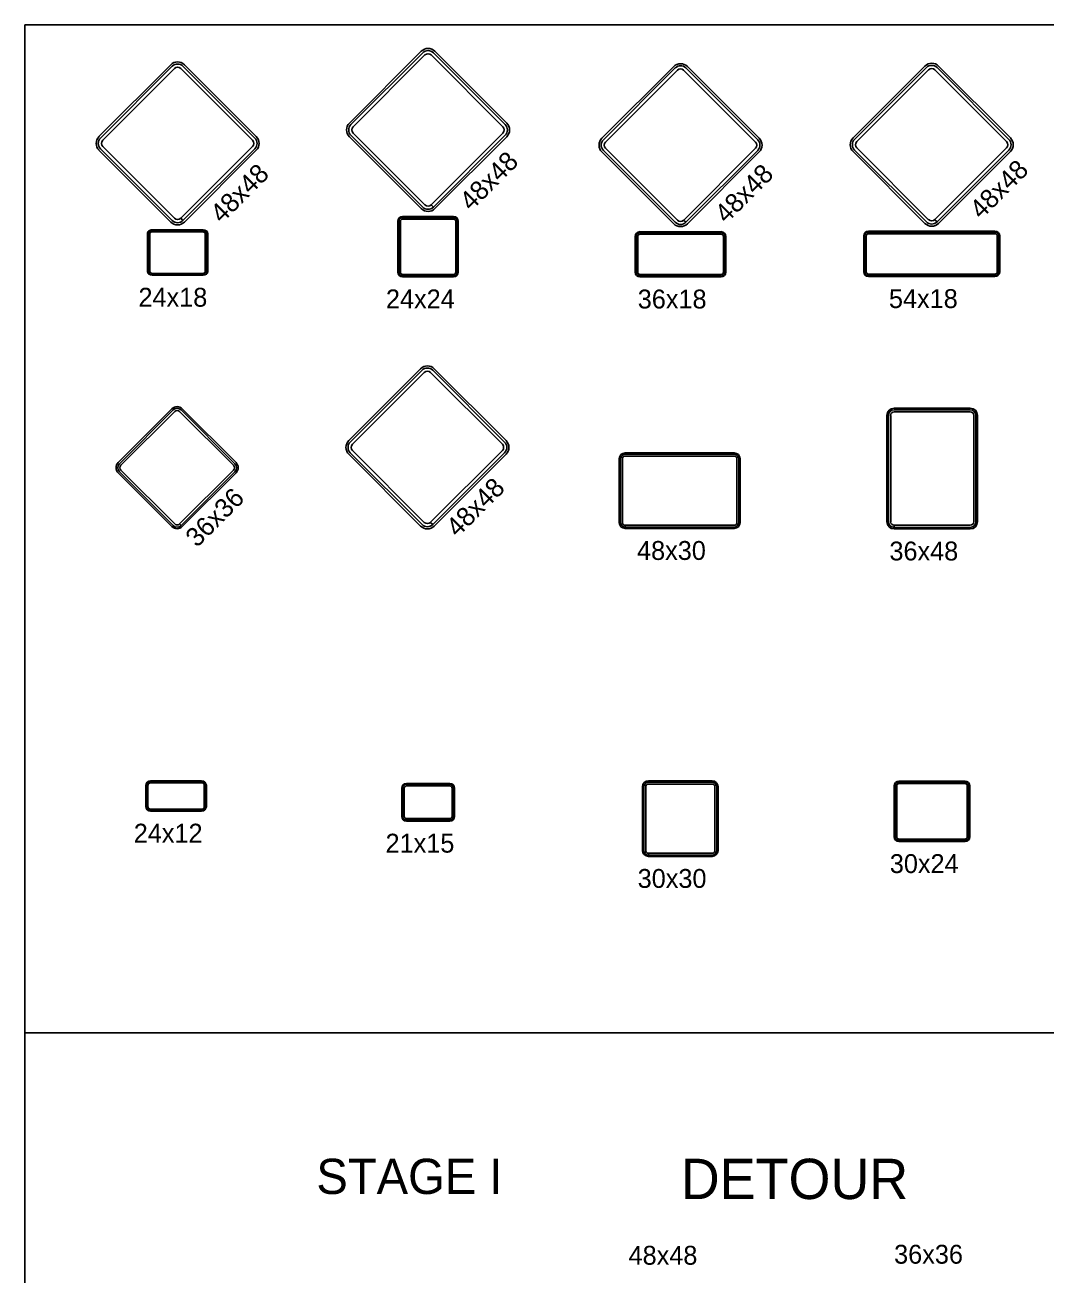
# Model space of a CAD drawing. Extents: x 1458 to 4498, y 17709 to 24109.
# Drawn here: x 1458 to 2268, y 18718 to 19709 of the extents above; entities that cross this region are included whole.
import ezdxf

# ---------------------------------------------------------------- set-up
doc = ezdxf.new("R2010")
doc.units = 0
for name, color, linetype in [('P_ODOT_PLAN_TBlock', 7, 'Continuous'), ('P_TRAF_TCP_General', 7, 'Continuous'), ('P_TRAF_TCP_GeneralTx', 7, 'Continuous')]:
    doc.layers.add(name, color=color, linetype=linetype)

msp = doc.modelspace()

# ---------------------------------------------------------------- linework, layer by layer
at = {"layer": 'P_ODOT_PLAN_TBlock'}
msp.add_line((1458.44, 18909.14), (2578.44, 18909.14), dxfattribs=at)
at = {"layer": 'P_TRAF_TCP_General'}
for p, q in [((1773.03, 19688.26), (1716.02, 19631.26)), ((1774.21, 19687.08), (1717.21, 19630.07)), ((1718.97, 19628.31), (1775.98, 19685.31)), ((1780.93, 19685.31), (1837.93, 19628.31)), ((1839.7, 19630.07), (1782.69, 19687.08)), ((1840.88, 19631.26), (1783.88, 19688.26)), ((1574.21, 19677.59), (1517.2, 19620.58)), ((1575.39, 19676.4), (1518.39, 19619.4)), ((1520.15, 19617.63), (1577.16, 19674.64)), ((1582.11, 19674.64), (1639.11, 19617.63)), ((1640.88, 19619.4), (1583.87, 19676.4)), ((1642.06, 19620.58), (1585.06, 19677.59)), ((1973.46, 19676.17), (1916.46, 19619.17)), ((1974.64, 19674.99), (1917.64, 19617.98)), ((1919.41, 19616.21), (1976.41, 19673.22)), ((1981.36, 19673.22), (2038.37, 19616.21)), ((1981.36, 19673.22), (2038.37, 19616.21)), ((2040.13, 19617.98), (1983.13, 19674.99)), ((2041.32, 19619.17), (1984.31, 19676.17)), ((2172.87, 19676.5), (2115.86, 19619.5)), ((2174.05, 19675.32), (2117.04, 19618.31)), ((2118.81, 19616.54), (2175.82, 19673.55)), ((2180.76, 19673.55), (2237.77, 19616.54)), ((2239.54, 19618.31), (2182.53, 19675.32)), ((2240.72, 19619.5), (2183.72, 19676.5)), ((1775.98, 19566.35), (1718.97, 19623.36)), ((1837.93, 19623.36), (1780.94, 19566.37)), ((1577.16, 19555.68), (1520.15, 19612.68)), ((1577.16, 19555.68), (1520.15, 19612.68)), ((1639.11, 19612.68), (1582.12, 19555.7)), ((1716.02, 19620.41), (1773.03, 19563.4)), ((1717.21, 19621.59), (1774.21, 19564.59)), ((1782.71, 19564.61), (1839.7, 19621.59)), ((1783.88, 19563.4), (1840.88, 19620.41)), ((1517.2, 19609.73), (1574.21, 19552.73)), ((1518.39, 19610.92), (1575.39, 19553.91)), ((1583.89, 19553.93), (1640.88, 19610.92)), ((1585.06, 19552.73), (1642.06, 19609.73)), ((1916.46, 19608.32), (1973.46, 19551.31)), ((1917.64, 19609.5), (1974.64, 19552.49)), ((1976.41, 19554.26), (1919.41, 19611.27)), ((2038.37, 19611.27), (1981.38, 19554.28)), ((1983.14, 19552.51), (2040.13, 19609.5)), ((1984.31, 19551.31), (2041.32, 19608.32)), ((2115.86, 19608.65), (2172.87, 19551.64)), ((2117.04, 19609.83), (2174.05, 19552.82)), ((2175.82, 19554.59), (2118.81, 19611.6)), ((2237.77, 19611.6), (2180.78, 19554.61)), ((2182.55, 19552.84), (2239.54, 19609.83)), ((2183.72, 19551.64), (2240.72, 19608.65)), ((1782.69, 19564.59), (1780.93, 19566.35)), ((1782.69, 19564.59), (1780.93, 19566.35)), ((1780.94, 19566.37), (1782.71, 19564.61)), ((1780.94, 19566.37), (1782.71, 19564.61)), ((1583.87, 19553.91), (1582.11, 19555.68)), ((1583.87, 19553.91), (1582.11, 19555.68)), ((1582.12, 19555.7), (1583.89, 19553.93)), ((1582.12, 19555.7), (1583.89, 19553.93)), ((1754.46, 19553.36), (1754.46, 19512.98)), ((1755.26, 19553.3), (1755.26, 19512.92)), ((1755.26, 19553.3), (1755.26, 19512.92)), ((1756.51, 19512.92), (1756.51, 19553.3)), ((1798.64, 19557.16), (1758.26, 19557.16)), ((1798.64, 19556.3), (1758.26, 19556.3)), ((1798.64, 19556.3), (1758.26, 19556.3)), ((1758.26, 19555.05), (1798.64, 19555.05)), ((1800.39, 19553.3), (1800.39, 19512.92)), ((1801.64, 19512.92), (1801.64, 19553.3)), ((1801.64, 19512.92), (1801.64, 19553.3)), ((1802.44, 19512.98), (1802.44, 19553.36)), ((1983.13, 19552.49), (1981.36, 19554.26)), ((1983.13, 19552.49), (1981.36, 19554.26)), ((1981.38, 19554.28), (1983.14, 19552.51)), ((1981.38, 19554.28), (1983.14, 19552.51)), ((2182.53, 19552.82), (2180.76, 19554.59)), ((2182.53, 19552.82), (2180.76, 19554.59)), ((2180.78, 19554.61), (2182.55, 19552.84)), ((2180.78, 19554.61), (2182.55, 19552.84)), ((1555.64, 19543.63), (1555.64, 19513.34)), ((1556.44, 19543.59), (1556.44, 19513.3)), ((1557.69, 19513.3), (1557.69, 19543.59)), ((1599.82, 19546.48), (1559.44, 19546.48)), ((1599.82, 19545.84), (1559.44, 19545.84)), ((1559.44, 19544.9), (1599.82, 19544.9)), ((1601.57, 19543.59), (1601.57, 19513.3)), ((1602.82, 19513.3), (1602.82, 19543.59)), ((1603.62, 19513.34), (1603.62, 19543.63)), ((2011.12, 19545.06), (1946.65, 19545.06)), ((2011.12, 19544.32), (1946.65, 19544.32)), ((1946.65, 19543.07), (2011.12, 19543.07)), ((2228.52, 19545.4), (2128.06, 19545.4)), ((2228.52, 19544.65), (2128.06, 19544.65)), ((2228.52, 19543.4), (2128.06, 19543.4)), ((2128.06, 19543.4), (2228.52, 19543.4)), ((1942.9, 19541.32), (1942.9, 19512.83)), ((1943.65, 19541.32), (1943.65, 19512.83)), ((1944.9, 19512.83), (1944.9, 19541.32)), ((2012.87, 19541.32), (2012.87, 19512.83)), ((2014.12, 19512.83), (2014.12, 19541.32)), ((2014.87, 19512.83), (2014.87, 19541.32)), ((2124.31, 19541.65), (2124.31, 19513.16)), ((2125.06, 19541.65), (2125.06, 19513.16)), ((2126.31, 19541.65), (2126.31, 19513.16)), ((2126.31, 19513.16), (2126.31, 19541.65)), ((2230.27, 19513.16), (2230.27, 19541.65)), ((2230.27, 19541.65), (2230.27, 19513.16)), ((2231.52, 19513.16), (2231.52, 19541.65)), ((2232.27, 19513.16), (2232.27, 19541.65)), ((1559.44, 19511.05), (1559.44, 19511.99)), ((1559.44, 19510.5), (1599.82, 19510.5)), ((1599.82, 19511.99), (1559.45, 19511.99)), ((1559.45, 19511.99), (1559.45, 19511.05)), ((1559.45, 19511.05), (1599.82, 19511.05)), ((1758.26, 19509.92), (1758.26, 19511.17)), ((1758.26, 19509.92), (1798.64, 19509.92)), ((1758.26, 19509.18), (1798.64, 19509.18)), ((1798.64, 19511.17), (1758.27, 19511.17)), ((1758.27, 19511.17), (1758.27, 19509.92)), ((1758.27, 19509.92), (1798.64, 19509.92)), ((1946.65, 19509.83), (1946.65, 19511.08)), ((1946.65, 19509.08), (2011.12, 19509.08)), ((2011.12, 19511.08), (1946.66, 19511.08)), ((1946.66, 19511.08), (1946.66, 19509.83)), ((1946.66, 19509.83), (2011.12, 19509.83)), ((2128.06, 19511.41), (2228.52, 19511.41)), ((2128.06, 19510.16), (2128.06, 19511.41)), ((2128.06, 19509.41), (2228.52, 19509.41)), ((2228.52, 19511.41), (2128.07, 19511.41)), ((2128.07, 19511.41), (2128.07, 19510.16)), ((2128.07, 19510.16), (2228.52, 19510.16)), ((1772.53, 19436.24), (1715.52, 19379.23)), ((1773.71, 19435.05), (1716.71, 19378.05)), ((1839.2, 19378.05), (1782.19, 19435.05)), ((1840.38, 19379.23), (1783.38, 19436.24)), ((1718.47, 19376.28), (1775.48, 19433.29)), ((1780.43, 19433.29), (1837.43, 19376.28)), ((1575.12, 19404.48), (1532.43, 19361.79)), ((1626.01, 19361.79), (1583.32, 19404.48)), ((2208.93, 19405.01), (2148.45, 19405.01)), ((2208.93, 19403.76), (2148.45, 19403.76)), ((1576.04, 19403.56), (1533.35, 19360.87)), ((1576.04, 19403.56), (1533.35, 19360.87)), ((1534.58, 19359.63), (1577.28, 19402.33)), ((1581.16, 19402.33), (1623.86, 19359.63)), ((1625.09, 19360.87), (1582.4, 19403.56)), ((1625.09, 19360.87), (1582.4, 19403.56)), ((2142.71, 19399.26), (2142.71, 19314.79)), ((2143.96, 19399.26), (2143.96, 19314.79)), ((2145.71, 19314.79), (2145.71, 19399.26)), ((2148.45, 19402.01), (2208.93, 19402.01)), ((2211.68, 19399.26), (2211.68, 19314.79)), ((2213.43, 19314.79), (2213.43, 19399.26)), ((2214.68, 19314.79), (2214.68, 19399.26)), ((1715.52, 19368.38), (1772.53, 19311.38)), ((1716.71, 19369.56), (1773.71, 19312.56)), ((1716.71, 19369.56), (1773.71, 19312.56)), ((1775.48, 19314.33), (1718.47, 19371.33)), ((1837.43, 19371.33), (1780.44, 19314.34)), ((1782.21, 19312.58), (1839.2, 19369.56)), ((1783.38, 19311.38), (1840.38, 19368.38)), ((1930.21, 19364.71), (1930.21, 19314.23)), ((1931.21, 19364.71), (1931.21, 19314.23)), ((1932.71, 19314.23), (1932.71, 19364.71)), ((2021.42, 19369.45), (1934.95, 19369.45)), ((2021.42, 19368.46), (1934.95, 19368.46)), ((1934.95, 19366.96), (2021.42, 19366.96)), ((2023.67, 19364.71), (2023.67, 19314.23)), ((2025.17, 19314.23), (2025.17, 19364.71)), ((2026.17, 19314.23), (2026.17, 19364.71)), ((1533.35, 19354.51), (1576.04, 19311.82)), ((1533.35, 19354.51), (1576.04, 19311.82)), ((1577.28, 19313.05), (1534.58, 19355.75)), ((1623.86, 19355.75), (1581.18, 19313.07)), ((1582.4, 19311.82), (1625.09, 19354.51)), ((1582.41, 19311.83), (1625.09, 19354.51)), ((1532.43, 19353.59), (1575.12, 19310.9)), ((1583.32, 19310.9), (1626.01, 19353.59)), ((1582.4, 19311.82), (1581.16, 19313.05)), ((1581.18, 19313.07), (1582.41, 19311.83)), ((1782.19, 19312.56), (1780.43, 19314.33)), ((1782.19, 19312.56), (1780.43, 19314.33)), ((1780.44, 19314.34), (1782.21, 19312.58)), ((1780.44, 19314.34), (1782.21, 19312.58)), ((1934.95, 19310.48), (1934.95, 19311.98)), ((1934.96, 19309.48), (2021.42, 19309.48)), ((2021.42, 19311.98), (1934.97, 19311.98)), ((1934.97, 19311.98), (1934.97, 19310.48)), ((1934.97, 19310.48), (2021.42, 19310.48)), ((2148.45, 19310.3), (2148.45, 19312.04)), ((2148.46, 19309.05), (2208.93, 19309.05)), ((2208.93, 19312.04), (2148.47, 19312.04)), ((2148.47, 19312.04), (2148.47, 19310.3)), ((2148.47, 19310.3), (2208.93, 19310.3)), ((1598.68, 19109.07), (1558.2, 19109.07)), ((1598.68, 19108.33), (1558.2, 19108.33)), ((1558.2, 19107.45), (1598.68, 19107.45)), ((1795.73, 19107.12), (1761.24, 19107.12)), ((1795.73, 19106.37), (1761.24, 19106.37)), ((2003.93, 19109.11), (1953.45, 19109.11)), ((2003.93, 19108.11), (1953.45, 19108.11)), ((2003.93, 19108.11), (1953.45, 19108.11)), ((1953.45, 19106.61), (2003.93, 19106.61)), ((2204.72, 19108.9), (2152.24, 19108.9)), ((2204.72, 19108.15), (2152.24, 19108.15)), ((2152.24, 19106.9), (2204.72, 19106.9)), ((1554.45, 19105.33), (1554.45, 19088.83)), ((1555.2, 19105.33), (1555.2, 19088.83)), ((1556.08, 19088.83), (1556.08, 19105.33)), ((1600.81, 19105.33), (1600.81, 19088.83)), ((1601.68, 19088.83), (1601.68, 19105.33)), ((1602.43, 19088.83), (1602.43, 19105.33)), ((1757.5, 19103.37), (1757.5, 19080.88)), ((1758.25, 19103.37), (1758.25, 19080.88)), ((1759.49, 19080.88), (1759.49, 19103.37)), ((1761.24, 19105.12), (1795.73, 19105.12)), ((1797.48, 19103.37), (1797.48, 19080.88)), ((1798.73, 19080.88), (1798.73, 19103.37)), ((1799.48, 19080.88), (1799.48, 19103.37)), ((1948.7, 19104.36), (1948.7, 19053.88)), ((1949.7, 19104.36), (1949.7, 19053.88)), ((1949.7, 19104.36), (1949.7, 19053.88)), ((1951.2, 19053.88), (1951.2, 19104.36)), ((2006.18, 19104.36), (2006.18, 19053.88)), ((2007.68, 19053.88), (2007.68, 19104.36)), ((2007.68, 19053.88), (2007.68, 19104.36)), ((2008.68, 19053.88), (2008.68, 19104.36)), ((2148.49, 19105.15), (2148.49, 19064.67)), ((2149.24, 19105.15), (2149.24, 19064.67)), ((2150.49, 19064.67), (2150.49, 19105.15)), ((2206.47, 19105.15), (2206.47, 19064.67)), ((2207.72, 19064.67), (2207.72, 19105.15)), ((2208.47, 19064.67), (2208.47, 19105.15)), ((1558.2, 19085.83), (1558.2, 19086.71)), ((1598.68, 19086.71), (1558.21, 19086.71)), ((1558.21, 19086.71), (1558.21, 19085.83)), ((1558.2, 19085.08), (1598.68, 19085.08)), ((1558.21, 19085.83), (1598.68, 19085.83)), ((1761.24, 19077.88), (1761.24, 19079.13)), ((1761.24, 19077.13), (1795.73, 19077.13)), ((1795.73, 19079.13), (1761.26, 19079.13)), ((1761.26, 19079.13), (1761.26, 19077.88)), ((1761.26, 19077.88), (1795.73, 19077.88)), ((2152.24, 19061.67), (2152.24, 19062.92)), ((2152.24, 19060.92), (2204.72, 19060.92)), ((2204.72, 19062.92), (2152.25, 19062.92)), ((2152.25, 19062.92), (2152.25, 19061.67)), ((2152.25, 19061.67), (2204.72, 19061.67)), ((1953.45, 19050.13), (1953.45, 19051.63)), ((1953.45, 19050.13), (2003.93, 19050.13)), ((1953.45, 19049.13), (2003.93, 19049.13)), ((2003.93, 19051.63), (1953.46, 19051.63)), ((1953.46, 19051.63), (1953.46, 19050.13)), ((1953.46, 19050.13), (2003.93, 19050.13))]:
    msp.add_line(p, q, dxfattribs=at)
msp.add_lwpolyline([(1458.44, 19709.14), (4498.44, 19709.14), (4498.44, 17709.14), (1458.44, 17709.14)], close=True, dxfattribs=at)
for centre, radius, start, end in [((1778.45, 19682.84), 7.67, 45, 135), ((1778.45, 19682.84), 6, 45, 135), ((1778.45, 19682.84), 3.5, 45, 135), ((1579.63, 19672.16), 7.67, 45, 135), ((1579.63, 19672.16), 6, 45, 135), ((1579.63, 19672.16), 3.5, 45, 135), ((1978.89, 19670.75), 7.67, 45, 135), ((1978.89, 19670.75), 6, 45, 135), ((1978.89, 19670.75), 3.5, 45, 135), ((2178.29, 19671.08), 7.67, 45, 135), ((2178.29, 19671.08), 6, 45, 135), ((2178.29, 19671.08), 3.5, 45, 135), ((1721.45, 19625.83), 7.67, 135, 225), ((1721.45, 19625.83), 6, 135, 225), ((1721.45, 19625.83), 3.5, 135, 225), ((1835.46, 19625.83), 3.5, 315, 45), ((1835.46, 19625.83), 6, 315, 45), ((1835.46, 19625.83), 7.67, 315, 45), ((1522.63, 19615.16), 7.67, 135, 225), ((1522.63, 19615.16), 6, 135, 225), ((1522.63, 19615.16), 6, 135, 225), ((1522.63, 19615.16), 3.5, 135, 225), ((1636.64, 19615.16), 3.5, 315, 45), ((1636.64, 19615.16), 6, 315, 45), ((1636.64, 19615.16), 7.67, 315, 45), ((1921.88, 19613.74), 7.67, 135, 225), ((1921.88, 19613.74), 6, 135, 225), ((1921.88, 19613.74), 6, 135, 225), ((1921.88, 19613.74), 3.5, 135, 225), ((2035.89, 19613.74), 3.5, 315, 45), ((2035.89, 19613.74), 6, 315, 45), ((2035.89, 19613.74), 7.67, 315, 45), ((2121.29, 19614.07), 7.67, 135, 225), ((2121.29, 19614.07), 6, 135, 225), ((2121.29, 19614.07), 3.5, 135, 225), ((2235.3, 19614.07), 3.5, 315, 45), ((2235.3, 19614.07), 6, 315, 45), ((2235.3, 19614.07), 7.67, 315, 45), ((1778.45, 19568.83), 7.67, 225, 315), ((1778.45, 19568.83), 6, 225, 315), ((1778.45, 19568.83), 6, 225, 315), ((1778.45, 19568.83), 3.5, 225, 315), ((1579.63, 19558.15), 7.67, 225, 315), ((1579.63, 19558.15), 6, 225, 315), ((1579.63, 19558.15), 3.5, 225, 315), ((1758.26, 19553.36), 3.8, 90, 180), ((1758.26, 19553.3), 3, 90, 180), ((1758.26, 19553.3), 3, 90, 180), ((1758.26, 19553.3), 1.75, 90, 180), ((1798.64, 19553.36), 3.8, 0, 90), ((1798.64, 19553.3), 3, 0, 90), ((1798.64, 19553.3), 3, 0, 90), ((1798.64, 19553.3), 1.75, 0, 90), ((1978.89, 19556.74), 6, 225, 315), ((1978.89, 19556.74), 3.5, 225, 315), ((2178.29, 19557.07), 6, 225, 315), ((2178.29, 19557.07), 3.5, 225, 315), ((1946.65, 19541.32), 3.75, 90, 180), ((1946.65, 19541.32), 3, 90, 180), ((1946.65, 19541.32), 1.75, 90, 180), ((1978.89, 19556.74), 7.67, 225, 315), ((2011.12, 19541.32), 3.75, 0, 90), ((2011.12, 19541.32), 3, 0, 90), ((2011.12, 19541.32), 1.75, 0, 90), ((2128.06, 19541.65), 3.75, 90, 180), ((2128.06, 19541.65), 3, 90, 180), ((2128.06, 19541.65), 1.75, 90, 180), ((2128.06, 19541.65), 1.75, 90, 180), ((2178.29, 19557.07), 7.67, 225, 315), ((2228.52, 19541.65), 3.75, 0, 90), ((2228.52, 19541.65), 3, 0, 90), ((2228.52, 19541.65), 1.75, 0, 90), ((2228.52, 19541.65), 1.75, 0, 90), ((1758.26, 19512.98), 3.8, 180, 270), ((1758.26, 19512.92), 3, 180, 270), ((1758.26, 19512.92), 3, 180, 270), ((1758.26, 19512.92), 1.75, 180, 270), ((1798.64, 19512.98), 3.8, 270, 0), ((1798.64, 19512.92), 3, 270, 0), ((1798.64, 19512.92), 3, 270, 0), ((1798.64, 19512.92), 1.75, 270, 0), ((1946.65, 19512.83), 3.75, 180, 270), ((1946.65, 19512.83), 3, 180, 270), ((1946.65, 19512.83), 1.75, 180, 270), ((2011.12, 19512.83), 3, 270, 0), ((2011.12, 19512.83), 1.75, 270, 0), ((2011.12, 19512.83), 3.75, 270, 0), ((2128.06, 19513.16), 3.75, 180, 270), ((2128.06, 19513.16), 3, 180, 270), ((2128.06, 19513.16), 1.75, 180, 270), ((2128.06, 19513.16), 1.75, 180, 270), ((2228.52, 19513.16), 1.75, 270, 0), ((2228.52, 19513.16), 3, 270, 0), ((2228.52, 19513.16), 1.75, 270, 0), ((2228.52, 19513.16), 3.75, 270, 0), ((1777.95, 19430.81), 7.67, 45, 135), ((1777.95, 19430.81), 6, 45, 135), ((1777.95, 19430.81), 3.5, 45, 135), ((1579.22, 19400.38), 5.8, 45, 135), ((1579.22, 19400.38), 4.5, 45, 135), ((1579.22, 19400.38), 4.5, 45, 135), ((2148.45, 19399.26), 5.75, 90, 180), ((2148.45, 19399.26), 4.5, 90, 180), ((2208.93, 19399.26), 5.75, 0, 90), ((2208.93, 19399.26), 4.5, 0, 90), ((1579.22, 19400.38), 2.75, 45, 135), ((2148.45, 19399.26), 2.75, 90, 180), ((2208.93, 19399.26), 2.75, 0, 90), ((1720.95, 19373.81), 7.67, 135, 225), ((1720.95, 19373.81), 6, 135, 225), ((1720.95, 19373.81), 3.5, 135, 225), ((1834.96, 19373.81), 3.5, 315, 45), ((1834.96, 19373.81), 6, 315, 45), ((1834.96, 19373.81), 7.67, 315, 45), ((1934.95, 19364.71), 4.75, 90, 180), ((1934.95, 19364.71), 3.75, 90, 180), ((1934.95, 19364.71), 2.25, 90, 180), ((2021.42, 19364.71), 4.75, 0, 90), ((2021.42, 19364.71), 3.75, 0, 90), ((2021.42, 19364.71), 2.25, 0, 90), ((1536.53, 19357.69), 5.8, 135, 225), ((1536.53, 19357.69), 4.5, 135, 225), ((1536.53, 19357.69), 4.5, 135, 225), ((1536.53, 19357.69), 2.75, 135, 225), ((1621.91, 19357.69), 2.75, 315, 45), ((1621.91, 19357.69), 4.5, 315, 45), ((1621.91, 19357.69), 4.5, 315, 45), ((1621.91, 19357.69), 5.8, 315, 45), ((2148.45, 19314.79), 5.75, 180, 270), ((2148.45, 19314.79), 4.5, 180, 270), ((2148.45, 19314.79), 2.75, 180, 270), ((2208.93, 19314.79), 4.5, 270, 0), ((2208.93, 19314.79), 2.75, 270, 0), ((2208.93, 19314.79), 5.75, 270, 0), ((1579.22, 19315), 5.8, 225, 315), ((1579.22, 19315), 4.5, 225, 315), ((1579.22, 19315), 4.5, 225, 315), ((1579.22, 19315), 2.75, 225, 315), ((1777.95, 19316.8), 7.67, 225, 315), ((1777.95, 19316.8), 6, 225, 315), ((1777.95, 19316.8), 3.5, 225, 315), ((1934.95, 19314.23), 4.75, 180, 270), ((1934.95, 19314.23), 3.75, 180, 270), ((1934.95, 19314.23), 2.25, 180, 270), ((2021.42, 19314.23), 3.75, 270, 0), ((2021.42, 19314.23), 2.25, 270, 0), ((2021.42, 19314.23), 4.75, 270, 0), ((1558.2, 19105.33), 3.75, 90, 180), ((1558.2, 19105.33), 3, 90, 180), ((1558.2, 19105.33), 2.12, 90, 180), ((1598.68, 19105.33), 3.75, 0, 90), ((1598.68, 19105.33), 3, 0, 90), ((1598.68, 19105.33), 2.12, 0, 90), ((1761.24, 19103.37), 3.75, 90, 180), ((1761.24, 19103.37), 3, 90, 180), ((1795.73, 19103.37), 3.75, 0, 90), ((1795.73, 19103.37), 3, 0, 90), ((1953.45, 19104.36), 4.75, 90, 180), ((1953.45, 19104.36), 4.75, 90, 180), ((1953.45, 19104.36), 3.75, 90, 180), ((1953.45, 19104.36), 3.75, 90, 180), ((1953.45, 19104.36), 2.25, 90, 180), ((2003.93, 19104.36), 4.75, 0, 90), ((2003.93, 19104.36), 3.75, 0, 90), ((2003.93, 19104.36), 3.75, 0, 90), ((2003.93, 19104.36), 2.25, 0, 90), ((2152.24, 19105.15), 3.75, 90, 180), ((2152.24, 19105.15), 3, 90, 180), ((2152.24, 19105.15), 1.75, 90, 180), ((2204.72, 19105.15), 3.75, 0, 90), ((2204.72, 19105.15), 3, 0, 90), ((2204.72, 19105.15), 1.75, 0, 90), ((1761.24, 19103.37), 1.75, 90, 180), ((1795.73, 19103.37), 1.75, 0, 90), ((1558.2, 19088.83), 3.75, 180, 270), ((1558.2, 19088.83), 3, 180, 270), ((1558.2, 19088.83), 2.12, 180, 270), ((1598.68, 19088.83), 3, 270, 0), ((1598.68, 19088.83), 2.12, 270, 0), ((1598.68, 19088.83), 3.75, 270, 0), ((1761.24, 19080.88), 3.75, 180, 270), ((1761.24, 19080.88), 3, 180, 270), ((1761.24, 19080.88), 1.75, 180, 270), ((1795.73, 19080.88), 3, 270, 0), ((1795.73, 19080.88), 1.75, 270, 0), ((1795.73, 19080.88), 3.75, 270, 0), ((2152.24, 19064.67), 3.75, 180, 270), ((2152.24, 19064.67), 3, 180, 270), ((2152.24, 19064.67), 1.75, 180, 270), ((2204.72, 19064.67), 3, 270, 0), ((2204.72, 19064.67), 1.75, 270, 0), ((2204.72, 19064.67), 3.75, 270, 0), ((1953.45, 19053.88), 4.75, 180, 270), ((1953.45, 19053.88), 3.75, 180, 270), ((1953.45, 19053.88), 3.75, 180, 270), ((1953.45, 19053.88), 2.25, 180, 270), ((2003.93, 19053.88), 3.75, 270, 0), ((2003.93, 19053.88), 3.75, 270, 0), ((2003.93, 19053.88), 2.25, 270, 0), ((2003.93, 19053.88), 4.75, 270, 0)]:
    msp.add_arc(centre, radius, start, end, dxfattribs=at)
for centre, major_axis, start_param, end_param in [((1559.44, 19543.63), (3.8, 0), 1.570796, 3.141593), ((1559.44, 19543.59), (3, 0), 1.570796, 3.141593), ((1559.44, 19543.59), (1.75, 0), 1.570796, 3.141593), ((1599.82, 19543.63), (3.8, 0), 0, 1.570796), ((1599.82, 19543.59), (3, 0), 0, 1.570796), ((1599.82, 19543.59), (1.75, 0), 0, 1.570796), ((1559.44, 19513.34), (3.8, 0), 3.141593, 4.712389), ((1559.44, 19513.3), (3, 0), 3.141593, 4.712389), ((1559.44, 19513.3), (1.75, 0), 3.141593, 4.712389), ((1599.82, 19513.34), (3.8, 0), 4.712389, 6.283185), ((1599.82, 19513.3), (3, 0), 4.712389, 6.283185), ((1599.82, 19513.3), (1.75, 0), 4.712389, 6.283185)]:
    msp.add_ellipse(centre, major_axis=major_axis, ratio=0.75, start_param=start_param, end_param=end_param, dxfattribs=at)

# ---------------------------------------------------------------- texts
for s, p in [('48x48', (1812.57, 19560.9)), ('48x48', (1614.63, 19551.1)), ('48x48', (2015.14, 19550.94)), ('48x48', (2217.56, 19554.28)), ('48x48', (1801.87, 19301.84)), ('36x36', (1595.02, 19293.8))]:
    msp.add_text(s, height=14.994, rotation=45, dxfattribs=at).set_placement(p)
for s, height, p in [('24x18', 14.994, (1548.53, 19485.51)), ('24x24', 14.994, (1745.01, 19484.19)), ('36x18', 14.994, (1944.91, 19484.09)), ('54x18', 14.994, (2144.32, 19484.42)), ('48x30', 14.994, (1944.35, 19284.49)), ('36x48', 14.994, (2144.72, 19284.06)), ('24x12', 14.994, (1544.79, 19060.09)), ('21x15', 14.994, (1744.7, 19052.14)), ('30x24', 14.994, (2145.03, 19035.93)), ('30x30', 14.994, (1944.85, 19024.14)), ('STAGE I', 27.989, (1689.79, 18781.15)), ('DETOUR', 31.987, (1979.07, 18777.15)), ('48x48', 14.994, (1937.63, 18725.01))]:
    msp.add_text(s, height=height, dxfattribs=at).set_placement(p)
at = {"layer": 'P_TRAF_TCP_GeneralTx'}
msp.add_text('36x36', height=15, dxfattribs=at).set_placement((2148.44, 18725.84))

doc.saveas('drawing.dxf')
